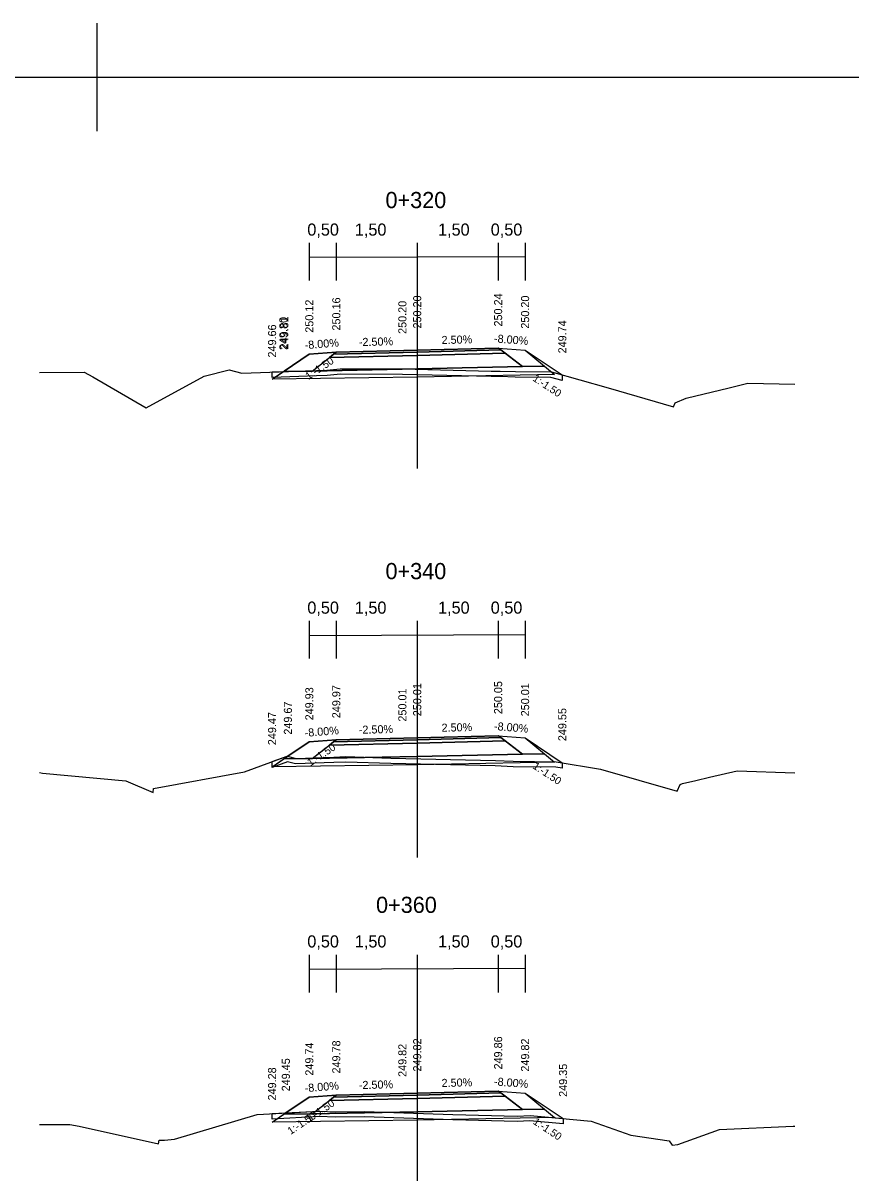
# Model space of a CAD drawing. Extents: x -552501 to -552394, y -1029983 to -1029892.
# Drawn here: x -552438.12 to -552422.78, y -1029913.82 to -1029892.35 of the extents above; entities that cross this region are included whole.
import ezdxf

# ---------------------------------------------------------------- set-up
doc = ezdxf.new("R2010")
doc.units = 0
for name, color, linetype in [('1', 7, 'Continuous'), ('16', 7, 'Continuous'), ('60', 7, 'Continuous'), ('9', 7, 'Continuous'), ('FORMATY', 7, 'Continuous'), ('Implicitní', 7, 'Continuous'), ('rámeček', 7, 'Continuous')]:
    doc.layers.add(name, color=color, linetype=linetype)

msp = doc.modelspace()

# ---------------------------------------------------------------- linework, layer by layer
for points in [[(-552433.505, -1029898.95), (-552433.297, -1029898.811), (-552433.28, -1029898.8), (-552432.815, -1029898.49), (-552432.315, -1029898.45), (-552430.815, -1029898.412), (-552429.315, -1029898.375), (-552428.815, -1029898.415), (-552428.125, -1029898.874)], [(-552437.815, -1029898.83), (-552436.988, -1029898.82), (-552436.829, -1029898.909), (-552435.841, -1029899.483), (-552434.762, -1029898.894), (-552434.302, -1029898.777), (-552434.065, -1029898.838), (-552432.682, -1029898.79), (-552432.493, -1029898.783), (-552432.244, -1029898.759), (-552431.088, -1029898.762), (-552429.441, -1029898.8), (-552429.276, -1029898.8), (-552428.995, -1029898.812), (-552428.326, -1029898.818), (-552427.277, -1029899.112), (-552426.067, -1029899.462), (-552426.036, -1029899.39), (-552425.83, -1029899.302), (-552425.035, -1029899.112), (-552424.688, -1029899.026), (-552423.815, -1029899.044)], [(-552433.505, -1029906.138), (-552433.212, -1029905.943), (-552432.815, -1029905.678), (-552432.315, -1029905.638), (-552430.815, -1029905.601), (-552429.315, -1029905.563), (-552428.815, -1029905.603), (-552428.125, -1029906.063)], [(-552437.815, -1029906.246), (-552437.762, -1029906.257), (-552436.214, -1029906.397), (-552435.709, -1029906.616), (-552435.706, -1029906.544), (-552434.016, -1029906.233), (-552433.226, -1029905.94), (-552433.06, -1029905.982), (-552432.363, -1029905.958), (-552432.138, -1029905.951), (-552431.301, -1029905.979), (-552429.364, -1029906.023), (-552429.034, -1029906.037), (-552428.238, -1029906.044), (-552427.416, -1029906.183), (-552425.995, -1029906.593), (-552425.942, -1029906.47), (-552425.899, -1029906.451), (-552425.651, -1029906.392), (-552425.398, -1029906.332), (-552424.882, -1029906.215), (-552423.815, -1029906.249)], [(-552433.505, -1029912.726), (-552433.25, -1029912.557), (-552432.815, -1029912.266), (-552432.315, -1029912.226), (-552430.815, -1029912.189), (-552429.315, -1029912.151), (-552428.815, -1029912.191), (-552428.112, -1029912.659)], [(-552437.815, -1029912.769), (-552437.254, -1029912.77), (-552437.083, -1029912.8), (-552435.609, -1029913.133), (-552435.601, -1029913.059), (-552435.497, -1029913.063), (-552435.312, -1029913.043), (-552433.782, -1029912.585), (-552432.634, -1029912.524), (-552432.33, -1029912.535), (-552431.792, -1029912.529), (-552430.153, -1029912.583), (-552428.965, -1029912.618), (-552428.723, -1029912.604), (-552427.59, -1029912.707), (-552426.854, -1029912.97), (-552426.144, -1029913.076), (-552426.09, -1029913.154), (-552425.986, -1029913.143), (-552425.213, -1029912.866), (-552423.848, -1029912.8), (-552423.815, -1029912.8)]]:
    msp.add_lwpolyline(points)
for points in [[(-552432.315, -1029898.45), (-552432.815, -1029898.49), (-552433.28, -1029898.8), (-552432.765, -1029898.8)], [(-552432.765, -1029898.8), (-552432.443, -1029898.55), (-552430.815, -1029898.512), (-552429.187, -1029898.469), (-552428.865, -1029898.719), (-552430.815, -1029898.762)], [(-552430.815, -1029898.452), (-552432.366, -1029898.49), (-552432.443, -1029898.55), (-552430.815, -1029898.512), (-552429.187, -1029898.469), (-552429.264, -1029898.409), (-552430.815, -1029898.452), (-552429.264, -1029898.409), (-552429.315, -1029898.375), (-552430.815, -1029898.412), (-552432.315, -1029898.45), (-552432.366, -1029898.49)], [(-552432.443, -1029898.55), (-552432.366, -1029898.49), (-552430.815, -1029898.452), (-552429.264, -1029898.409), (-552429.187, -1029898.469), (-552430.815, -1029898.512)], [(-552429.315, -1029898.375), (-552428.815, -1029898.415), (-552428.454, -1029898.712), (-552428.865, -1029898.719), (-552429.187, -1029898.469), (-552429.264, -1029898.409)], [(-552433.505, -1029898.95), (-552433.28, -1029898.8), (-552432.765, -1029898.8), (-552430.815, -1029898.762), (-552428.865, -1029898.719), (-552428.454, -1029898.712), (-552428.269, -1029898.862), (-552430.815, -1029898.912)], [(-552433.505, -1029898.818), (-552432.682, -1029898.79), (-552432.493, -1029898.783), (-552432.244, -1029898.759), (-552431.088, -1029898.762), (-552429.441, -1029898.8), (-552429.276, -1029898.8), (-552428.995, -1029898.812), (-552428.326, -1029898.818), (-552428.125, -1029898.874), (-552428.125, -1029898.978), (-552428.341, -1029898.918), (-552428.998, -1029898.912), (-552429.278, -1029898.9), (-552429.442, -1029898.9), (-552431.09, -1029898.862), (-552432.239, -1029898.859), (-552432.486, -1029898.883), (-552432.679, -1029898.89), (-552433.505, -1029898.918)], [(-552430.815, -1029905.641), (-552432.366, -1029905.678), (-552432.443, -1029905.738), (-552430.815, -1029905.701), (-552429.187, -1029905.657), (-552429.264, -1029905.597), (-552430.815, -1029905.641), (-552429.264, -1029905.597), (-552429.315, -1029905.563), (-552430.815, -1029905.601), (-552432.315, -1029905.638), (-552432.366, -1029905.678)], [(-552432.443, -1029905.738), (-552432.366, -1029905.678), (-552430.815, -1029905.641), (-552429.264, -1029905.597), (-552429.187, -1029905.657), (-552430.815, -1029905.701)], [(-552429.315, -1029905.563), (-552428.815, -1029905.603), (-552428.454, -1029905.901), (-552428.865, -1029905.907), (-552429.187, -1029905.657), (-552429.264, -1029905.597)], [(-552432.315, -1029905.638), (-552432.815, -1029905.678), (-552433.28, -1029905.988), (-552432.765, -1029905.988)], [(-552432.765, -1029905.988), (-552432.443, -1029905.738), (-552430.815, -1029905.701), (-552429.187, -1029905.657), (-552428.865, -1029905.907), (-552430.815, -1029905.951)], [(-552433.505, -1029906.138), (-552433.28, -1029905.988), (-552432.765, -1029905.988), (-552430.815, -1029905.951), (-552428.865, -1029905.907), (-552428.454, -1029905.901), (-552428.269, -1029906.051), (-552430.815, -1029906.101)], [(-552433.505, -1029906.043), (-552433.226, -1029905.94), (-552433.06, -1029905.982), (-552432.363, -1029905.958), (-552432.138, -1029905.951), (-552431.301, -1029905.979), (-552429.364, -1029906.023), (-552429.034, -1029906.037), (-552428.238, -1029906.044), (-552428.125, -1029906.063), (-552428.125, -1029906.164), (-552428.247, -1029906.144), (-552429.036, -1029906.137), (-552429.367, -1029906.123), (-552431.304, -1029906.079), (-552432.138, -1029906.051), (-552432.36, -1029906.058), (-552433.071, -1029906.083), (-552433.221, -1029906.044), (-552433.505, -1029906.15)], [(-552432.315, -1029912.226), (-552432.815, -1029912.266), (-552433.28, -1029912.576), (-552432.765, -1029912.576)], [(-552432.765, -1029912.576), (-552432.443, -1029912.326), (-552430.815, -1029912.289), (-552429.187, -1029912.245), (-552428.865, -1029912.495), (-552430.815, -1029912.539)], [(-552430.815, -1029912.229), (-552432.366, -1029912.266), (-552432.443, -1029912.326), (-552430.815, -1029912.289), (-552429.187, -1029912.245), (-552429.264, -1029912.185), (-552430.815, -1029912.229), (-552429.264, -1029912.185), (-552429.315, -1029912.151), (-552430.815, -1029912.189), (-552432.315, -1029912.226), (-552432.366, -1029912.266)], [(-552432.443, -1029912.326), (-552432.366, -1029912.266), (-552430.815, -1029912.229), (-552429.264, -1029912.185), (-552429.187, -1029912.245), (-552430.815, -1029912.289)], [(-552429.315, -1029912.151), (-552428.815, -1029912.191), (-552428.454, -1029912.489), (-552428.865, -1029912.495), (-552429.187, -1029912.245), (-552429.264, -1029912.185)], [(-552433.505, -1029912.726), (-552433.28, -1029912.576), (-552432.765, -1029912.576), (-552430.815, -1029912.539), (-552428.865, -1029912.495), (-552428.454, -1029912.489), (-552428.269, -1029912.639), (-552430.815, -1029912.689)], [(-552433.505, -1029912.57), (-552432.634, -1029912.524), (-552432.33, -1029912.535), (-552431.792, -1029912.529), (-552430.153, -1029912.583), (-552428.965, -1029912.618), (-552428.723, -1029912.604), (-552428.112, -1029912.659), (-552428.112, -1029912.76), (-552428.725, -1029912.704), (-552428.964, -1029912.718), (-552430.156, -1029912.683), (-552431.793, -1029912.629), (-552432.331, -1029912.635), (-552432.633, -1029912.624), (-552433.505, -1029912.67)]]:
    msp.add_lwpolyline(points, close=True)
at = {"layer": '60'}
for p, q in [((-552430.815, -1029896.61), (-552430.815, -1029900.61)), ((-552430.815, -1029903.61), (-552430.815, -1029907.823)), ((-552430.815, -1029910.009), (-552430.815, -1029913.816))]:
    msp.add_line(p, q, dxfattribs=at)
at = {"layer": '9'}
for p, q in [((-552432.815, -1029896.425), (-552432.815, -1029897.122)), ((-552432.315, -1029896.425), (-552432.315, -1029897.122)), ((-552430.815, -1029896.425), (-552430.815, -1029897.925)), ((-552429.315, -1029896.425), (-552429.315, -1029897.122)), ((-552428.815, -1029896.425), (-552428.815, -1029897.122)), ((-552432.815, -1029903.435), (-552432.815, -1029904.132)), ((-552432.315, -1029903.435), (-552432.315, -1029904.132)), ((-552430.815, -1029903.435), (-552430.815, -1029904.935)), ((-552429.315, -1029903.435), (-552429.315, -1029904.132)), ((-552428.815, -1029903.435), (-552428.815, -1029904.132)), ((-552432.815, -1029909.624), (-552432.815, -1029910.322)), ((-552432.315, -1029909.624), (-552432.315, -1029910.322)), ((-552430.815, -1029909.624), (-552430.815, -1029911.124)), ((-552429.315, -1029909.624), (-552429.315, -1029910.322)), ((-552428.815, -1029909.624), (-552428.815, -1029910.322))]:
    msp.add_line(p, q, dxfattribs=at)
at = {"layer": 'FORMATY'}
for p, q in [((-552436.755, -1029892.35), (-552436.755, -1029894.35)), ((-552437.755, -1029893.35), (-552435.755, -1029893.35))]:
    msp.add_line(p, q, dxfattribs=at)
at = {"layer": 'Implicitní'}
for p, q in [((-552432.805, -1029896.692), (-552428.815, -1029896.675)), ((-552432.805, -1029903.702), (-552428.815, -1029903.685)), ((-552432.805, -1029909.892), (-552428.815, -1029909.874))]:
    msp.add_line(p, q, dxfattribs=at)
at = {"layer": 'rámeček'}
msp.add_line((-552499.755, -1029893.35), (-552394.755, -1029893.35), dxfattribs=at)

# ---------------------------------------------------------------- texts
for rotation, p in [(33.6902, (-552432.831, -1029898.969)), (326.3098, (-552428.686, -1029898.969)), (33.6902, (-552432.797, -1029906.135)), (326.3098, (-552428.686, -1029906.158)), (33.6902, (-552432.816, -1029912.736)), (33.69, (-552433.161, -1029912.966)), (326.3098, (-552428.68, -1029912.75))]:
    msp.add_text('1:-1.50', height=0.14, rotation=rotation).set_placement(p)
at = {"layer": '1'}
for s, p in [('0+320', (-552431.403, -1029895.78)), ('0+340', (-552431.403, -1029902.66)), ('0+360', (-552431.578, -1029908.848))]:
    msp.add_text(s, height=0.3, dxfattribs=at).set_placement(p)
at = {"layer": '16'}
for s, p in [('0,50', (-552432.852, -1029896.29)), ('1,50', (-552431.971, -1029896.29)), ('1,50', (-552430.429, -1029896.29)), ('0,50', (-552429.452, -1029896.29)), ('0,50', (-552432.852, -1029903.3)), ('1,50', (-552431.971, -1029903.3)), ('1,50', (-552430.429, -1029903.3)), ('0,50', (-552429.452, -1029903.3)), ('0,50', (-552432.852, -1029909.489)), ('1,50', (-552431.971, -1029909.489)), ('1,50', (-552430.429, -1029909.489)), ('0,50', (-552429.452, -1029909.489))]:
    msp.add_text(s, height=0.225, dxfattribs=at).set_placement(p)
for s, rotation, p in [('250.16', 90, (-552432.24, -1029898.05)), ('250.20', 90, (-552430.74, -1029898.012)), ('250.24', 90, (-552429.24, -1029897.975)), ('250.20', 90, (-552428.74, -1029898.015)), ('250.12', 90, (-552432.74, -1029898.09)), ('250.20', 90, (-552431.015, -1029898.112)), ('249.80', 90, (-552433.222, -1029898.411)), ('249.81', 90, (-552433.205, -1029898.4)), ('249.74', 90, (-552428.05, -1029898.474)), ('249.66', 90, (-552433.43, -1029898.55)), ('-8.00%', 4.5739, (-552432.896, -1029898.396)), ('-2.50%', 1.4321, (-552431.896, -1029898.339)), ('2.50%', 1.4321, (-552430.362, -1029898.301)), ('-8.00%', 355.4261, (-552429.396, -1029898.268)), ('249.93', 90, (-552432.74, -1029905.278)), ('249.97', 90, (-552432.24, -1029905.238)), ('250.01', 90, (-552431.015, -1029905.301)), ('250.01', 90, (-552430.74, -1029905.201)), ('250.05', 90, (-552429.24, -1029905.163)), ('250.01', 90, (-552428.74, -1029905.203)), ('249.67', 90, (-552433.137, -1029905.543)), ('249.47', 90, (-552433.43, -1029905.738)), ('249.55', 90, (-552428.05, -1029905.663)), ('-8.00%', 4.5739, (-552432.896, -1029905.585)), ('-2.50%', 1.4321, (-552431.896, -1029905.528)), ('2.50%', 1.4321, (-552430.362, -1029905.49)), ('-8.00%', 355.4261, (-552429.396, -1029905.457)), ('249.82', 90, (-552430.74, -1029911.789)), ('249.86', 90, (-552429.24, -1029911.751)), ('249.82', 90, (-552428.74, -1029911.791)), ('249.74', 90, (-552432.74, -1029911.866)), ('249.78', 90, (-552432.24, -1029911.826)), ('249.82', 90, (-552431.015, -1029911.889)), ('249.45', 90, (-552433.175, -1029912.157)), ('249.28', 90, (-552433.43, -1029912.326)), ('249.35', 90, (-552428.037, -1029912.259)), ('-8.00%', 4.5739, (-552432.896, -1029912.173)), ('-2.50%', 1.4321, (-552431.896, -1029912.116)), ('2.50%', 1.4321, (-552430.362, -1029912.077)), ('-8.00%', 355.4261, (-552429.396, -1029912.045))]:
    msp.add_text(s, height=0.15, rotation=rotation, dxfattribs=at).set_placement(p)

doc.saveas('drawing.dxf')
